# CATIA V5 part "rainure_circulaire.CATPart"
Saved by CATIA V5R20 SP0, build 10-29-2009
Part number: rainure_circulaire
Bounding box of the stored display mesh (mm): x 0 to 20, y 50 to 150, z -49.99 to 49.99
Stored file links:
  D:\Dropbox\IAO_2012\IAO_2012_991_jambrosino\IAO_2012_991_jambrosino_Catia\Assemblage\rainure_circulaire.CATPart
  D:\Dropbox\IAO_2012\IAO_2012_991_jambrosino\IAO_2012_991_jambrosino_Catia\Assemblage\Ass_IAO_991_skl.CATProduct
  J:\IAO_Mecanisme_991\IAO_Mecanisme_991_CATIA\skl_rainure_circulaire.CATPart
  J:\IAO_Mecanisme_991\IAO_Mecanisme_991_CATIA\skl_bielle_2.CATPart
  D:\Dropbox\IAO_2012\IAO_2012_991_jambrosino\IAO_2012_991_jambrosino_Catia\Assemblage\bati.CATPart
  D:\Dropbox\IAO_2012\IAO_2012_991_jambrosino\IAO_2012_991_jambrosino_Catia\Assemblage\excentrique.CATPart
  J:\IAO_Mecanisme_991\IAO_Mecanisme_991_CATIA\skl_bati.CATPart
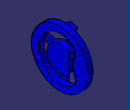
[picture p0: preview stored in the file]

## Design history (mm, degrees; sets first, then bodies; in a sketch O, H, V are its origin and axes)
Set1
  Plane1 "plan_ref_yz": linked copy from another document
  DatumPoint1: linked copy from another document
  DatumCurve1: linked copy from another document
  Line1: linked copy from another document
  DatumPoint2: linked copy from another document
  DatumSurface1: linked copy from another document
Body1 (main body)
  DatumCurve2
  Scaling1: Reference DatumPoint1, Ratio 1.25, ToTransfor DatumCurve2
  Plane2: type Offset, RefPlane Plane1, Offset 8
  Scaling2: Reference DatumPoint1, Ratio 0.75, ToTransfor DatumCurve1
  Scaling3: Reference DatumPoint1, Ratio 1.25, ToTransfor DatumCurve2
  Circle1: type CtrRad, Start 0, End 360, Center DatumPoint1, Support yz-plane, Radius 50, FirstDirection (0, 1, 0)
  Pad1: profile Circle1, length 10
  Pocket1: profile Scaling3, through (limit type 6)
  Pad2: profile Scaling2, length 10
  Translate1: Direction end face of Pad1, Length -10, ToTransfor Pad2
  Sketch1 on start face of Pad1, origin (10, 0, 0), H (0, -1, 0), V (0, 0, 1)
    arc A1 centre (-100, 0) radius 48 from (-100, 48) to (-114.8158, 45.6562) ccw
    point P1 (-100, 0)
    point P2 (-100, 48)
    point P3 (-114.8158, 45.6562)
    reference projected point E1 (-100, 0) from DatumPoint1
    arc A2 centre (-100, 0) radius 42 from (-100, 42) to (-112.9638, 39.9492) ccw
    point P4 (-100, 0)
    reference projected point E2 (-100, 0) from DatumPoint1
    line L1 (-100, 48) -> (-100, 42)
    line L2 (-114.8158, 45.6562) -> (-112.9638, 39.9492)
    point P7 (-114.8158, 45.6562)
    reference projected point E3 (-100, 0) from DatumPoint1
    reference projected point E4 (-100, 0) from DatumPoint1
    arc A3 centre (-100, 0) radius 16 from (-100, 16) to (-104.9386, 15.2188) ccw
    point P8 (-100, 0)
    reference projected point E5 (-100, 0) from DatumPoint1
    arc A4 centre (-100, 0) radius 20 from (-100, 20) to (-106.1732, 19.0234) ccw
    point P11 (-100, 0)
    point P13 (-106.1732, 19.0234)
    line L3 (-100, 20) -> (-100, 16)
    line L4 (-104.9386, 15.2188) -> (-106.1732, 19.0234)
    point P14 (-106.1732, 19.0234)
    radius A1 = 48
    radius A2 = 42
    radius A1 = 48 (reference)
    distance P3 P2 = 15
    radius A3 = 16
    radius A4 = 20
    coincidence: E1 P1, P4 E2, P7 A1, L2 E3, L1 E4, P3 P7, P8 E5, P11 P8, P14 L2, L3 L1, L4 L2, P13 P14
    vertical: L1 V
  Pad3: profile Sketch1, direction (-1, 0, 0), length 3
  Sketch2 on end face of Pad3, origin (7, 0, 0), H (0, -1, 0), V (0, 0, 1)
    arc A1 centre (-100, 0) radius 48 from (-100, 48) to (-114.8158, 45.6562) ccw
    point P1 (-100, 0)
    point P2 (-100, 48)
    point P3 (-114.8158, 45.6562)
    reference projected arc E1 centre (-100, 0) radius 48 from (-100, 48) to (-114.8158, 45.6562) ccw from edge [face of Pad3 from Sketch1.A1 | end face of Pad3]
    reference projected point E2 (-100, 48) from vertex [face of Pad3 from Sketch1.L1 | face of Pad3 from Sketch1.A1 | end face of Pad3]
    reference projected point E3 (-114.8158, 45.6562) from edge [face of Pad3 from Sketch1.L2 | face of Pad3 from Sketch1.A1]
    arc A2 centre (-100, 0) radius 16 from (-100, 16) to (-104.9386, 15.2187) ccw
    point P4 (-100, 0)
    point P5 (-100, 16)
    point P6 (-104.9386, 15.2188)
    reference projected point E4 (-100, 16) from vertex [face of Pad3 from Sketch1.A3 | face of Pad3 from Sketch1.L3 | end face of Pad3]
    reference projected point E5 (-104.9386, 15.2188) from vertex [face of Pad3 from Sketch1.L4 | face of Pad3 from Sketch1.A3 | end face of Pad3]
    line L1 (-100, 48) -> (-100, 16)
    line L2 (-114.8158, 45.6563) -> (-104.9386, 15.2188)
    coincidence: A1 E1, P2 E2, P3 E3, P4 P1, P5 E4, E5 P6, L2 P1
    vertical: L1 V
  Pad4: profile Sketch2, direction (-1, 0, 0), length 5
  CircPattern1: of Pad4, instances 3, angular step 90, axis from Line1
  Sketch3 on start face of Pad2, origin (10, 0, 0), H (0, -1, 0), V (0, 0, 1)
    circle A1 centre (-100, 0) radius 7.5
    point P1 (-100, 0)
    reference projected point E1 (-100, 0) from DatumPoint2
    radius A1 = 7.5
    coincidence: P1 E1
  Pad5: profile Sketch3, direction (-1, 0, 0), up to face of DatumSurface1
  Plane3: type Offset, RefPlane start face of Pad1, Offset 0, reversed
  Project1: ToProject DatumCurve2, Support Plane3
